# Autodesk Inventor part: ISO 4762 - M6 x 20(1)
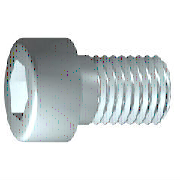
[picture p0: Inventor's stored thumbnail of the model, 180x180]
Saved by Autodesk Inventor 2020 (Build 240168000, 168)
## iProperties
Created: 2019-01
Part Number: ISO 4762 - M6 x 20(1)
Material: Nerezová ocel 440C
Description: Šroub s válcovou hlavou s vnitřním šestihranem
Document SubType Name: Modeling
Standard: ISO 4762
Designer: doma
Standard Revision: Fourth edition 2004-03-01
Standards Organization: ISO
Language: cs-CZ
Size Designation: M6 x 20
Categories: <MemberInstance><Categories><Category DisplayName="Spojovací materiál" InternalName="e4da775c-781d-43d5-af7c-5136215cf5a6" Mnemonic="FSTN"><Category DisplayName
Density: 7.75 g/cm^3
Appearance: Pololeštěná
IsCustomPart: 0
Author: doma
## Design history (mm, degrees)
sketch "Náčrt1"
  geometry: L1 (-1.333, 0)-(20, 0); L2 (20, 0)-(20, 3); L3 (20, 3)-(2.5, 3); L4 (2.5, 3)-(1.886, 3); L5 (1.886, 3)-(0, 3); L6 (0, 3)-(0, 5); L7 (0, 5)-(-6, 5); L8 (-6, 5)-(-6, 2.887); L9 (-6, 2.887)-(-3, 2.887); L10 (-3, 2.887)-(-1.333, 0); L11 (-11.2, 0)-(25.2, 0) reference; L12 (0, -1)-(0, 6) reference; L13 (2.5, 3)-(0, 3)
  constraints: 22 end point, 6 parallel, 2 collinear, 2 perpendicular, 1 horizontal, 1 point on line
  dimensions: "d1" = 17.5 distance from line of L3.end L2 (= GEL); "d2" = 0.61355 distance of L4.end L3.end (computed from GAL); "d3" = 6 distance between parallel lines of L8 L6 (= KOH); "d4" = 3 distance of L8.end L9.end (= INTI); "d5" = 60 deg angle of L10 L1; "d6" = 6 diameter of L3 L1 (= GD); "d7" = 6 diameter of L5 L1 (= BDM); "d8" = 5.7735 diameter of L9 L1 (= 1.1547 x SW); "d9" = 10 diameter of L7 L1 (= KOD); "d26" = 20 distance between parallel lines of L12 L2 (= NLG)
revolve "Těleso" sketch "Náčrt1" stored, may be unused: angle "d10" = 90 deg
sketch "Náčrt2"
  geometry: L1 (0, -7)-(0, 7) reference; L2 (-7, 0)-(7, 0) reference; L3 (2.887, 0)-(1.443, -2.5); L4 (1.443, -2.5)-(-1.443, -2.5); L5 (-1.443, -2.5)-(-2.887, 0); L6 (-2.887, 0)-(-1.443, 2.5); L7 (-1.443, 2.5)-(1.443, 2.5); L8 (1.443, 2.5)-(2.887, 0); 2 further points
  constraints: 12 end point, 1 coincident, 1 horizontal alignment, 1 point on line, 12 other
extrude "Drážka" join sketch "Náčrt2" stored distance "d11" = 10; taper "d12" = 0 deg
workplane "Work Plane1"
fillet "Fillet2" dims "d30" = 0.1 (= R)
body "Solid1"
fillet "Zaoblení1" dims "d17" = 0.6 (= RR)
feature "Závit" dims "d13" = 17.5 (= GEL), "d14" = 0
chamfer "Zkosení1" distance "d15" = 0.61345 (= -0.5 x SPD + 0.5 x GD); stored, may be unused: second distance "d16" = 0.61345 (= GUL), angle "d27" = 45 deg
other parameters: "GD" = 6 [user parameter; used in 2 equation terms], "NLG" = 20 [user parameter; used in 1 equation term], "GEL" = 17.5 [user parameter; used in 2 equation terms], "KOD" = 10 [user parameter; used in 1 equation term], "KOH" = 6 [user parameter; used in 1 equation term], "INTI" = 3 [user parameter; used in 1 equation term], "GAL" = 0.61345 (= 0.61345 x PTC) [user parameter; used in 1 equation term], "GUL" = 0.61345 (= 0.61345 x PTC) [user parameter; used in 1 equation term], "BDM" = 6 (= NND) [user parameter; used in 1 equation term], "SW" = 5 [user parameter; used in 2 equation terms], "RR" = 0.6 [user parameter; used in 1 equation term], "SPD" = 4.7731 (= NND - 1.2269 x PTC) [user parameter; used in 1 equation term], "d19" = 0, "d28" = 0, "d29" = 0, "R" = 0.1 [user parameter; used in 1 equation term], "TOA" = 30 deg [user parameter], "GD1" = 4.7731 (= THREADDIA - 1.2269 x PTC) [user parameter], "THREADDIA" = 6 [user parameter; used in 1 equation term], "FAWI" = 45 deg [user parameter], "PTC" = 1 [user parameter; used in 5 equation terms], "NND" = 6 [user parameter; used in 2 equation terms], "E0" = 5.775 (= 1.155 x SW) [user parameter]
